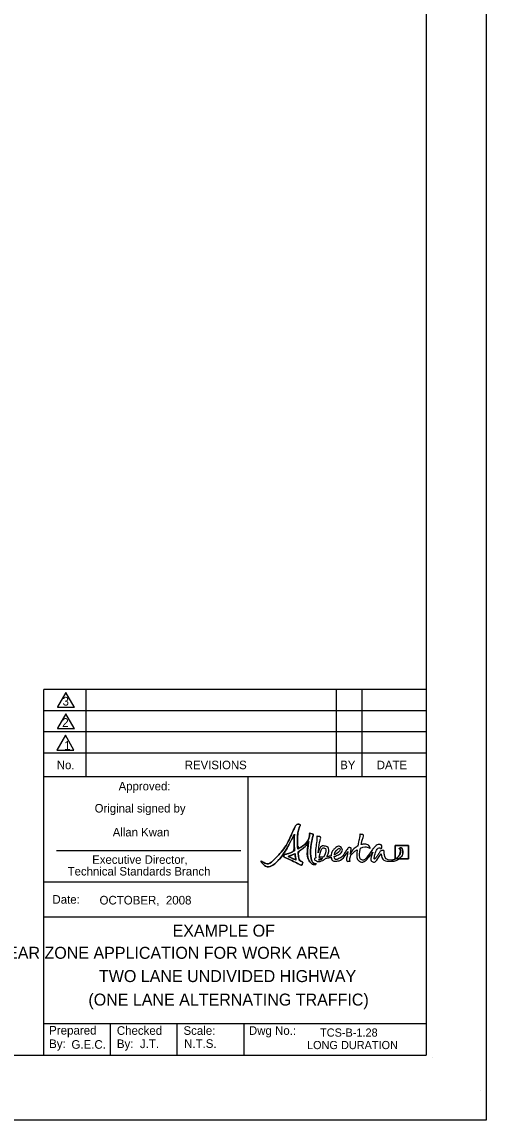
# Model space of a CAD drawing. Extents: x 2427 to 2645, y -255 to 24.
# Drawn here: x 2567.5 to 2645, y -255 to -71.9 of the extents above; entities that cross this region are included whole.
import ezdxf

# ---------------------------------------------------------------- set-up
doc = ezdxf.new("R2010")
doc.units = 0
for name, color, linetype in [('Level 1', 7, 'Continuous'), ('Level 17', 7, 'Continuous'), ('Level 22', 7, 'Continuous'), ('Level 36', 7, 'Continuous'), ('Level 44', 7, 'Continuous'), ('Level 5', 7, 'Continuous'), ('Level 53', 7, 'Continuous'), ('Level 60', 7, 'Continuous'), ('Level 7', 7, 'Continuous')]:
    doc.layers.add(name, color=color, linetype=linetype)

msp = doc.modelspace()

# ---------------------------------------------------------------- linework, layer by layer
at = {"layer": 'Level 1'}
for p, q in [((2634.98, -186.72), (2571.13, -186.72)), ((2634.98, -190.27), (2571.13, -190.27)), ((2634.98, -193.81), (2571.13, -193.81)), ((2571.13, -244.18), (2571.13, -197.71)), ((2571.13, -197.71), (2634.98, -197.71)), ((2605.18, -197.71), (2605.18, -221.12)), ((2571.13, -215.27), (2605.18, -215.27)), ((2571.13, -221.12), (2634.98, -221.12)), ((2571.13, -238.86), (2634.98, -238.86)), ((2582.27, -244.18), (2582.27, -238.86)), ((2593.4, -244.18), (2593.4, -238.86)), ((2604.52, -238.86), (2604.52, -244.18))]:
    msp.add_line(p, q, dxfattribs=at)
msp.add_lwpolyline([(2574.75, -190.83), (2573.33, -193.3), (2576.17, -193.3)], close=True, dxfattribs=at)
at = {"layer": 'Level 17'}
for p, q in [((2644.98, 24.01), (2644.98, -254.99)), ((2635.01, -183.16), (2571.13, -183.16)), ((2644.98, -254.99), (2428.98, -254.99))]:
    msp.add_line(p, q, dxfattribs=at)
at = {"layer": 'Level 22'}
for p, q in [((2634.98, 12.32), (2634.98, -244.18)), ((2447.52, -244.18), (2634.98, -244.18)), ((2586.6, -244.18), (2586.6, -244.18))]:
    msp.add_line(p, q, dxfattribs=at)
at = {"layer": 'Level 36'}
for p, q in [((2571.13, -189.64), (2571.13, -183.16)), ((2619.95, -183.16), (2619.95, -197.71)), ((2624.26, -183.16), (2624.26, -197.71))]:
    msp.add_line(p, q, dxfattribs=at)
at = {"layer": 'Level 5'}
msp.add_line((2644.1, -249.98), (2644.1, -249.98), dxfattribs=at)
at = {"layer": 'Level 53'}
msp.add_line((2630.41, -211.43), (2629.86, -211.43), dxfattribs=at)
msp.add_lwpolyline([(2630.41, -211.43), (2632.03, -211.43), (2632.03, -209.2), (2629.8, -209.2), (2629.8, -211.43), (2629.86, -211.43)], dxfattribs=at)
for points, degree in [([(2616.43, -212.24), (2616.19, -212.21), (2615.87, -211.88), (2615.78, -211.35), (2615.61, -210.38), (2615.71, -209.43), (2615.99, -208), (2616.04, -207.74), (2616.23, -207.27), (2615.64, -207.18), (2615.46, -207.15), (2615.56, -207.24), (2615.5, -207.49), (2615.28, -208.55), (2614.41, -209.31), (2613.54, -209.82), (2613.45, -208.61), (2613.49, -207.26), (2613.72, -206.44), (2613.91, -205.74), (2614.14, -205.87), (2613.86, -205.72), (2613.56, -205.57), (2613.24, -205.77), (2612.98, -206.29), (2612.72, -206.81), (2611.52, -209.63), (2609.61, -211.53), (2608.63, -212.5), (2607.75, -212), (2607.57, -211.85), (2607.42, -211.73), (2607.37, -211.92), (2607.55, -212.11), (2608.34, -212.96), (2609.5, -212.47), (2609.92, -212.05), (2611.08, -210.89), (2612.43, -208.39), (2612.98, -207.32), (2612.93, -207.92), (2612.91, -208.92), (2613.02, -210.1), (2612.43, -210.39), (2611.9, -210.56), (2611.65, -210.62), (2611.38, -210.69), (2611.21, -210.8), (2611.21, -210.93), (2611.2, -211.07), (2611.38, -211.18), (2611.65, -211.31), (2612.12, -211.53), (2613.49, -212.18), (2613.82, -212.38), (2614.11, -212.54), (2614.26, -212.41), (2614.34, -212.23), (2614.45, -212), (2614.15, -211.86), (2613.85, -211.77), (2613.73, -211.37), (2613.64, -210.84), (2613.58, -210.25), (2614.28, -209.82), (2614.97, -209.25), (2615.36, -208.53), (2615.26, -209.13), (2615.01, -211.16), (2615.65, -212.02), (2615.79, -212.21), (2616.1, -212.41), (2616.4, -212.38), (2616.55, -212.37), (2616.62, -212.27), (2616.61, -212.24), (2616.59, -212.22), (2616.51, -212.26), (2616.43, -212.24)], 3), ([(2613.54, -209.82), (2613.45, -208.61), (2613.49, -207.26), (2613.72, -206.44), (2613.91, -205.74), (2614.14, -205.87), (2613.86, -205.72), (2613.56, -205.57), (2613.24, -205.77), (2612.98, -206.29), (2612.72, -206.81), (2611.52, -209.63), (2609.61, -211.53), (2608.63, -212.5), (2607.75, -212), (2607.57, -211.85), (2607.42, -211.73), (2607.37, -211.92), (2607.55, -212.11), (2608.34, -212.96), (2609.5, -212.47), (2609.92, -212.05), (2611.08, -210.89), (2612.43, -208.39), (2612.98, -207.32)], 3), ([(2612.98, -207.32), (2612.93, -207.92), (2612.91, -208.92), (2613.02, -210.1)], 2), ([(2616.43, -212.24), (2616.19, -212.21), (2615.87, -211.88), (2615.78, -211.35), (2615.61, -210.38), (2615.71, -209.43), (2615.99, -208), (2616.04, -207.74), (2616.23, -207.27), (2615.64, -207.18), (2615.46, -207.15), (2615.56, -207.24), (2615.5, -207.49), (2615.28, -208.55), (2614.41, -209.31), (2613.54, -209.82)], 3), ([(2613.58, -210.25), (2614.28, -209.82), (2614.97, -209.25), (2615.36, -208.53)], 2), ([(2615.36, -208.53), (2615.26, -209.13), (2615.01, -211.16), (2615.65, -212.02), (2615.79, -212.21), (2616.1, -212.41), (2616.4, -212.38), (2616.55, -212.37), (2616.62, -212.27), (2616.61, -212.24), (2616.59, -212.22), (2616.51, -212.26), (2616.43, -212.24)], 3), ([(2616.96, -210.4), (2617.01, -209.83), (2617.1, -209.14), (2617.23, -208.5), (2617.28, -208.23), (2617.47, -207.76), (2616.88, -207.67), (2616.7, -207.65), (2616.72, -207.73), (2616.74, -207.98), (2616.76, -208.32), (2616.39, -210.36), (2616.58, -211.26)], 3), ([(2624.12, -209.06), (2624.18, -208.76), (2624.26, -208.46), (2624.34, -208.17), (2624.41, -207.9), (2624.64, -207.43), (2624.06, -207.34), (2623.88, -207.32), (2623.95, -207.4), (2623.89, -207.65), (2623.78, -208.11), (2623.64, -208.7), (2623.54, -209.3)], 3), ([(2613.02, -210.1), (2612.43, -210.39), (2611.9, -210.56), (2611.65, -210.62), (2611.38, -210.69), (2611.21, -210.8), (2611.21, -210.93), (2611.2, -211.07), (2611.38, -211.18), (2611.65, -211.31), (2612.12, -211.53), (2613.49, -212.18), (2613.82, -212.38), (2614.11, -212.54), (2614.26, -212.41), (2614.34, -212.23), (2614.45, -212), (2614.15, -211.86), (2613.85, -211.77)], 3), ([(2611.95, -211.03), (2612.26, -210.92), (2612.66, -210.75), (2613.07, -210.54)], 2), ([(2613.07, -210.54), (2613.13, -211.01), (2613.19, -211.35), (2613.25, -211.61)], 2), ([(2613.85, -211.77), (2613.73, -211.37), (2613.64, -210.84), (2613.58, -210.25)], 2), ([(2618.4, -211.06), (2618.81, -210.39), (2618.78, -209.48), (2618.17, -209.33), (2617.47, -209.15), (2617.11, -209.83), (2616.96, -210.4)], 3), ([(2617.11, -211.19), (2617.21, -210.48), (2617.58, -209.48), (2618.04, -209.64), (2618.31, -209.73), (2618.17, -210.57), (2617.83, -211.13)], 3), ([(2619.63, -211.04), (2619.72, -211.01), (2619.81, -210.98), (2619.88, -210.95), (2620.76, -210.56), (2621.07, -209.97), (2620.84, -209.61), (2620.63, -209.27), (2620.02, -209.37), (2619.54, -209.88), (2619.3, -210.13), (2619.12, -210.56), (2619.1, -210.95)], 3), ([(2619.11, -211.17), (2619.16, -211.56), (2619.41, -211.86), (2620.01, -211.81), (2620.85, -211.73), (2621.6, -210.69), (2621.89, -210.19)], 3), ([(2622.3, -210.63), (2622.36, -210.35), (2622.44, -210.04), (2622.45, -209.84), (2622.46, -209.62), (2622.31, -209.57), (2622.25, -209.56), (2622.12, -209.52), (2621.97, -209.58), (2621.82, -209.8), (2621.47, -210.29), (2621.02, -211.08), (2620.34, -211.41), (2619.85, -211.65), (2619.64, -211.41), (2619.63, -211.04)], 3), ([(2620.1, -209.92), (2620.39, -209.65), (2620.54, -209.67), (2620.58, -209.74), (2620.66, -209.9), (2620.32, -210.46), (2619.65, -210.77)], 3), ([(2619.65, -210.77), (2619.71, -210.47), (2619.87, -210.14), (2620.1, -209.92)], 2), ([(2621.89, -210.19), (2621.84, -210.72), (2621.49, -211.9), (2622.08, -211.83), (2622.32, -211.81), (2622.22, -211.77), (2622.23, -211.57), (2622.28, -210.87), (2622.87, -210.27), (2623.45, -209.9)], 3), ([(2623.54, -209.3), (2623.07, -209.57), (2622.62, -210.03), (2622.3, -210.63)], 2), ([(2623.45, -209.9), (2623.35, -210.77), (2623.39, -211.54), (2623.78, -211.78), (2624.5, -212.23), (2625.52, -211.05), (2626.09, -210.32)], 3), ([(2629.17, -211.63), (2628.26, -211.63), (2628.02, -210.92), (2627.98, -210.57), (2627.95, -210.34), (2628, -210), (2627.59, -210.04), (2627.31, -210.07), (2627.05, -210.62), (2626.69, -211.09), (2626.39, -211.49), (2626.25, -211.45), (2626.32, -211.11), (2626.41, -210.68), (2626.77, -209.67), (2627.18, -209.6), (2627.37, -209.57), (2627.43, -209.9), (2627.52, -209.69), (2627.61, -209.48), (2627.53, -209.03), (2627.1, -209.03), (2626.81, -209.03), (2626.45, -209.35), (2626.16, -209.7), (2625.91, -210.02), (2624.62, -211.91), (2624.08, -211.5), (2623.83, -211.31), (2623.85, -210.53), (2624.01, -209.62)], 3), ([(2624.01, -209.62), (2624.65, -209.37), (2625.18, -209.45), (2625.48, -209.59), (2625.63, -209.67), (2625.65, -209.65), (2625.59, -209.49), (2625.49, -209.25), (2624.98, -208.88), (2624.17, -209.05), (2624.16, -209.05), (2624.14, -209.06), (2624.12, -209.06)], 3), ([(2626.09, -210.32), (2625.8, -210.96), (2625.64, -211.79), (2626.07, -211.92), (2626.57, -212.07), (2626.97, -211.23), (2627.44, -210.59)], 3), ([(2627.44, -210.59), (2627.49, -211.05), (2627.8, -211.84), (2629.03, -211.84), (2629.59, -211.84), (2630.06, -211.68), (2630.41, -211.43)], 3), ([(2629.8, -209.2), (2629.8, -209.2), (2629.8, -211.43), (2629.8, -211.43), (2629.8, -211.43), (2629.86, -211.43), (2629.86, -211.43), (2630.34, -211.15), (2630.67, -210.59), (2630.67, -210.13), (2630.67, -209.74), (2630.46, -209.76), (2630.48, -209.71), (2630.55, -209.55), (2631.04, -209.64), (2631.07, -210.19), (2631.1, -210.67), (2630.85, -211.12), (2630.41, -211.43), (2630.41, -211.43), (2632.03, -211.43), (2632.03, -211.43), (2632.03, -211.43), (2632.03, -209.2), (2632.03, -209.2), (2632.03, -209.2), (2629.8, -209.2), (2629.8, -209.2)], 3), ([(2629.86, -211.43), (2630.34, -211.15), (2630.67, -210.59), (2630.67, -210.13), (2630.67, -209.74), (2630.46, -209.76), (2630.48, -209.71), (2630.55, -209.55), (2631.04, -209.64), (2631.07, -210.19), (2631.1, -210.67), (2630.85, -211.12), (2630.41, -211.43)], 3), ([(2611.95, -211.03), (2612.26, -210.92), (2612.66, -210.75), (2613.07, -210.54), (2613.13, -211.01), (2613.19, -211.35), (2613.25, -211.61), (2612.95, -211.5), (2612.52, -211.32), (2611.95, -211.03)], 3), ([(2613.25, -211.61), (2612.95, -211.5), (2612.52, -211.32), (2611.95, -211.03)], 2), ([(2616.58, -211.26), (2616.33, -211.34), (2616.23, -211.53), (2616.55, -211.72), (2616.78, -211.86), (2617.27, -211.91), (2617.76, -211.66), (2617.94, -211.58), (2618.09, -211.45), (2618.22, -211.31)], 3), ([(2617.04, -211.63), (2617.07, -211.6), (2617.09, -211.56), (2617.09, -211.51), (2617.09, -211.48), (2617.09, -211.45), (2617.09, -211.41)], 3), ([(2617.24, -211.62), (2617.16, -211.64), (2617.09, -211.64), (2617.04, -211.63)], 2), ([(2617.09, -211.41), (2617.22, -211.41), (2617.41, -211.39), (2617.65, -211.37)], 2), ([(2617.83, -211.13), (2617.6, -211.15), (2617.36, -211.17), (2617.11, -211.19)], 2), ([(2617.65, -211.37), (2617.53, -211.51), (2617.39, -211.6), (2617.24, -211.62)], 2), ([(2618.22, -211.31), (2618.51, -211.27), (2618.82, -211.22), (2619.11, -211.17)], 2), ([(2619.1, -210.95), (2618.9, -210.99), (2618.66, -211.03), (2618.4, -211.06)], 2), ([(2629.86, -211.43), (2629.65, -211.56), (2629.42, -211.63), (2629.17, -211.63)], 2)]:
    msp.add_open_spline(points, degree=degree, dxfattribs=at)
at = {"layer": 'Level 60'}
for p, q in [((2578.22, -197.71), (2578.22, -183.16)), ((2571.13, -189.64), (2571.13, -186.72)), ((2571.13, -197.71), (2571.13, -189.64)), ((2607.36, -211.87), (2607.48, -211.87)), ((2636.04, -244.53), (2636.04, -244.53))]:
    msp.add_line(p, q, dxfattribs=at)
for points in [[(2574.83, -183.67), (2573.44, -186.09)], [(2576.22, -186.09), (2574.83, -183.67)], [(2573.44, -186.09), (2573.41, -186.14), (2576.25, -186.14), (2576.22, -186.09)], [(2574.83, -187.22), (2573.44, -189.64)], [(2576.22, -189.64), (2574.83, -187.22)], [(2573.44, -189.64), (2573.41, -189.69), (2576.25, -189.69), (2576.22, -189.64)]]:
    msp.add_lwpolyline(points, dxfattribs=at)
at = {"layer": 'Level 7'}
msp.add_line((2573.24, -210.03), (2604.04, -210.03), dxfattribs=at)

# ---------------------------------------------------------------- texts
at = {"layer": 'Level 1'}
for s, height, p in [('3', 1.45, (2574.26, -185.87)), ('2', 1.45, (2574.21, -189.42)), ('1', 1.45, (2574.53, -193.24)), ('No.', 1.419, (2573.31, -196.48)), ('REVISIONS', 1.419, (2594.68, -196.48)), ('Date:', 1.433, (2572.57, -218.91)), ('Prepared', 1.44, (2572.02, -240.74)), ('Checked', 1.433, (2583.33, -240.78)), ('Scale:', 1.433, (2594.46, -240.78)), ('Dwg No.:', 1.433, (2605.38, -240.78)), ('By:', 1.44, (2572.02, -242.99)), ('By:  J.T.', 1.44, (2583.33, -242.99)), ('    N.T.S.   ', 1.4329, (2592.43, -242.95))]:
    msp.add_text(s, height=height, rotation=360, dxfattribs=at).set_placement(p)
msp.add_text('G.E.C.', height=1.433, dxfattribs=at).set_placement((2575.75, -243.1))
at = {"layer": 'Level 17'}
for s, p in [('BY', (2620.63, -196.48)), ('DATE', (2626.73, -196.48))]:
    msp.add_text(s, height=1.419, rotation=360, dxfattribs=at).set_placement(p)
at = {"layer": 'Level 44'}
for s, p in [('EXAMPLE OF', (2592.63, -224.4)), ('        CLEAR ZONE APPLICATION FOR WORK AREA', (2555.65, -228.1)), ('TWO LANE UNDIVIDED HIGHWAY', (2580.35, -231.98)), ('(ONE LANE ALTERNATING TRAFFIC)', (2578.58, -235.9))]:
    msp.add_text(s, height=2, dxfattribs=at).set_placement(p)
at = {"layer": 'Level 60'}
for s, height, p in [('OCTOBER,  2008', 1.434, (2580.44, -219.04)), ('TCS-B-1.28', 1.362, (2617.26, -241.08)), ('LONG DURATION', 1.3624, (2615.08, -243.16))]:
    msp.add_text(s, height=height, dxfattribs=at).set_placement(p)
at = {"layer": 'Level 7'}
for s, height, p in [('Approved:', 1.419, (2583.63, -200.01)), ('Original signed by', 1.4187, (2579.62, -203.7)), ('Allan Kwan', 1.419, (2582.64, -207.69)), ('Executive Director,', 1.4187, (2579.22, -212.26)), ('Technical Standards Branch', 1.4187, (2575.12, -214.21))]:
    msp.add_text(s, height=height, dxfattribs=at).set_placement(p)

doc.saveas('drawing.dxf')
